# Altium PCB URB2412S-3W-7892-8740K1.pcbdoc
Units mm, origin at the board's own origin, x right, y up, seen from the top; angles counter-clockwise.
Board outline 23.7 x 14.8 mm, 2 copper layers (Top Layer, Bottom Layer), stack 0.78 mm thick; 27 components, 19 nets, 72 pads, 28 vias.
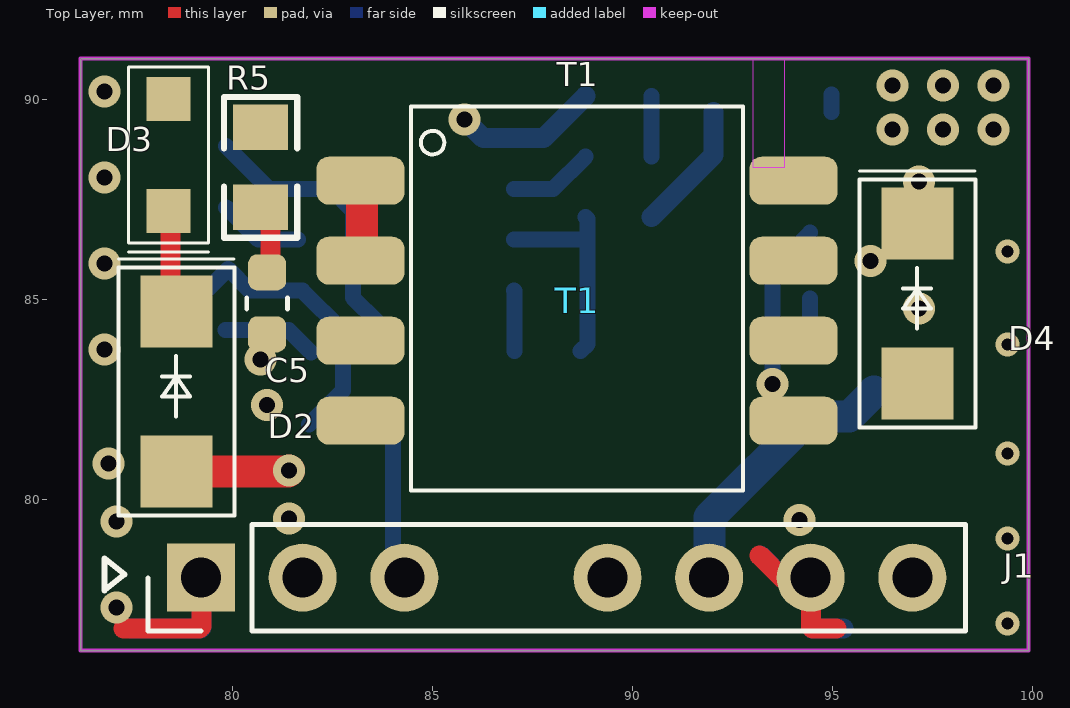
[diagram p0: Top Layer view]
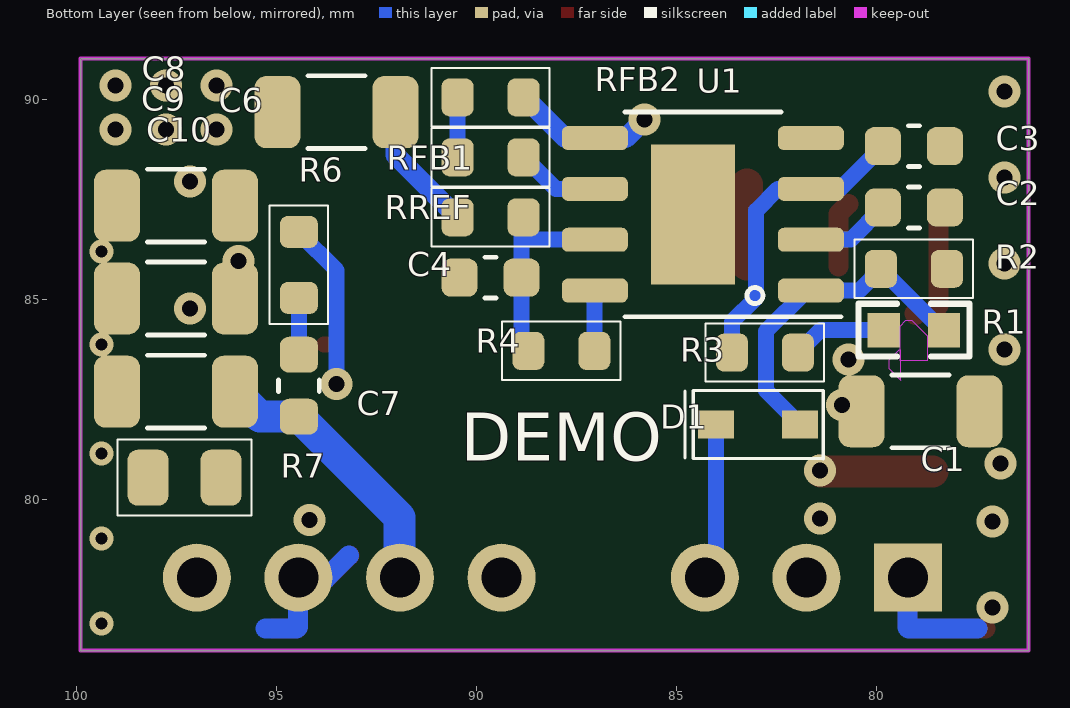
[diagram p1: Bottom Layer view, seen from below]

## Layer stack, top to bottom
Top Solder Mask Layer: solder mask 0.01, Dk 3.3
Top Layer: signal copper 0.035
Dielectric2: surface 0.71, FR4, Dk 4.5
Bottom Layer: signal copper 0.035
Bottom Solder Mask Layer: solder mask 0.01, Dk 3.3

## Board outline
76.2,91.02 99.9,91.02 99.9,76.22 76.2,76.22

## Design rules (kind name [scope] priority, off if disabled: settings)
BoardOutlineClearance copperThickness1oz [All] p0: genericclearance=0.254 ignorepadtopadclearanceinfootprint=FALSE except(0: Arc-SplitContinuation Track-SplitContinuation SMDPad-SplitContinuation THPad-SplitContinuation Via-SplitContinuation Fill-SplitContinuation Poly-SplitContinuation Region-SplitContinuation Text-SplitContinuation)
BoardOutlineClearance otherClearance [All] p0: genericclearance=0.254 ignorepadtopadclearanceinfootprint=FALSE except(0: Arc-SplitContinuation Track-SplitContinuation SMDPad-SplitContinuation THPad-SplitContinuation Via-SplitContinuation Fill-SplitContinuation Poly-SplitContinuation Region-SplitContinuation Text-SplitContinuation)
Clearance copperThickness1oz [All] p1: gap=0.178 ignorepadtopadclearanceinfootprint=FALSE
Clearance otherClearance [All] p1: gap=0.178 ignorepadtopadclearanceinfootprint=FALSE
DiffPairsRouting differentialPair [All] p1: maxuncoupledlength=10 minlimit=5 maxlimit=Infinity mostfreqgap=6 toplayer_minwidth=5 toplayer_prefwidth=100 toplayer_maxwidth=100 bottomlayer_minwidth=5 bottomlayer_prefwidth=100 bottomlayer_maxwidth=100
PasteMaskExpansion pasteMaskExpansion [All] p1: expansion=0
PlaneConnect innerPlane [All] p1: planeconnectstyle=Relief reliefexpansion=0.508 reliefentries=4 reliefconductorwidth=0.254 reliefairgap=0.254
PolygonConnect copper0 [All] p1: connectstyle=Relief reliefentries=4 reliefconductorwidth=19.685 polygonreliefangle="90 Angle" airgapwidth=19.685
PolygonConnect copper1 [All] p1: connectstyle=Direct reliefentries=4 reliefconductorwidth=10 polygonreliefangle="90 Angle" airgapwidth=10
RoutingVias viaSize [All] p1: viastyle="Through Hole" holewidth=24 minholewidth=11.811 maxholewidth=393.7 width=24 minwidth=11.811 maxwidth=393.7
SolderMaskExpansion solderMaskExpansion [All] p1: useseparateexpansions=TRUE expansion=2 expansionbottom=2
Width copperThickness1oz [All] p1: maxlimit=100 minlimit=5 preferedwidth=10

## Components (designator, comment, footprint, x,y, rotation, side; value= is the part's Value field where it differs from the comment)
C1 "10uF" C1206 78.9,82.2 r180 bottom
C2 "1uF" C0603 79.065,87.297 r0 bottom
C3 "1uF" C0603 79.065,88.83 r180 bottom
C4 "10pF" C0603 89.65,85.543 r180 bottom
C5 "470pF" C0603 80.865,84.9 r270 top
C6 "1nF" C1206 93.5,89.68 r180 bottom
C7 "My_library_C" coileasy:C_0603 94.44,82.84 r270 bottom
C8 "22uF" C1206 97.515,87.34 r0 bottom
C9 "22uF" C1206 97.515,85.02 r0 bottom
C10 "22uF" C1206 97.515,82.69 r0 bottom
D1 "B0540WS" SOD-323_L1.8-W1.3-LS2.5-RD 82.96,81.88 r180 bottom
D2 "1SMA5930A" SMA_L4.3-W2.6-LS5.2-RD 78.6,82.7 r270 top
D3 "DSS210" SOD-123_L2.8-W1.8-LS3.7-FD 78.452,88.71 r90 top
D4 "SS38" SMA_L4.4-W2.8-LS5.4-RD 97.121,84.9 r270 top
J1 "Coileasy_Conn_01x07_1" coileasy:PinHeader_01x07_1_P2.54mm_Vertical 79.214,78.042 r90 top
R1 "" R0603#1 79.065,84.23 r0 bottom
R2 "100kΩ" R0603#2 79.065,85.763 r0 bottom
R3 "0Ω" R0603#2 82.79,83.67 r180 bottom
R4 "Coileasy_R" coileasy:R_0603 87.88,83.71 r0 bottom
R5 "" R0805#1 80.7,88.3 r90 top
R6 "Coileasy_R" coileasy:R_0603 94.44,85.86 r90 bottom
R7 "2.2kΩ" R0805#2 97.3,80.54 r0 bottom
RFB1 "120kΩ" R0603#2 89.65,88.55 r180 bottom
RFB2 "4.7kΩ" R0603#2 89.65,90.05 r0 bottom
RREF "10kΩ" R0603#2 89.65,87.05 r180 bottom
T1 "" ? 88.358,84.9 r0 top
U1 "CMP7892" ESOP-8_L4.9-W3.9-P1.27-LS6.0-BL-EP3.3 84.34,87.125 r0 bottom

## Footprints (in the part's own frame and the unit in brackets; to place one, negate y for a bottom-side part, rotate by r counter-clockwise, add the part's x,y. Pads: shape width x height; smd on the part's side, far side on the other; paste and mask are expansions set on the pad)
C0603 [mm]
  rrect50% 0.9x0.95 smd: 1(-0.775,0) 2(0.775,0)
  silkscreen extent -0.14,-0.51 0.14,0.51
C1206 [mm]
  rrect50% 1.15x1.8 smd: 1(-1.475,0) 2(1.475,0)
  silkscreen extent -0.71,-0.91 0.71,0.91
coileasy:C_0603 [mm]
  rrect50% 0.9x0.95 smd: 1(-0.775,0) 2(0.775,0)
  silkscreen extent -0.14,-0.51 0.14,0.51
coileasy:PinHeader_01x07_1_P2.54mm_Vertical [mm]
  rect 1.7x1.7 hole 1: 1(0,0)
  round 1.7 hole 1: 2(0,-2.54) 3(0,-5.08) 5(0,-10.16) 6(0,-12.7) 7(0,-15.24) 8(0,-17.78)
  silkscreen extent -1.33,-19.11 1.33,1.33
coileasy:R_0603 [mm]
  rrect50% 0.8x0.95 smd: 1(-0.825,0) 2(0.825,0)
  silkscreen extent -1.48,-0.73 1.48,0.73
ESOP-8_L4.9-W3.9-P1.27-LS6.0-BL-EP3.3 [mm]
  rrect50% 1.65x0.6 smd: 1(-2.7,1.905) 2(-2.7,0.635) 3(-2.7,-0.635) 4(-2.7,-1.905) 5(2.7,-1.905) 6(2.7,-0.635) 7(2.7,0.635) 8(2.7,1.905)
  rect 2.1x3.5 smd: 9(0.25,0)
  silkscreen extent -3.45,-2.56 1.95,2.56
R0603#1 [mm]
  rect 0.806x0.864 smd: 1(-0.753,0) 2(0.753,0)
  silkscreen extent -1.39,-0.66 1.39,0.66
R0603#2 [mm]
  rrect50% 0.8x0.95 smd: 1(-0.825,0) 2(0.825,0)
  silkscreen extent -1.48,-0.73 1.48,0.73
R0805#1 [mm]
  rect 1.133x1.377 smd: 1(-1,0) 2(1,0)
  silkscreen extent -1.76,-0.92 1.76,0.92
R0805#2 [mm]
  rrect50% 1.025x1.4 smd: 1(-0.913,0) 2(0.913,0)
  silkscreen extent -1.68,-0.95 1.68,0.95
SMA_L4.3-W2.6-LS5.2-RD [mm]
  rect 1.8x1.8 smd: 1(-2,0) 2(2,0)
  silkscreen extent -3.31,-1.45 3.1,1.45
SMA_L4.4-W2.8-LS5.4-RD [mm]
  rect 1.8x1.8 smd: 1(-2,0) 2(2,0)
  silkscreen extent -3.31,-1.45 3.1,1.45
SOD-123_L2.8-W1.8-LS3.7-FD [mm]
  rect 1.1x1.1 smd: 1(-1.5,0.05) 2(1.3,0.05)
  silkscreen extent -2.53,-0.95 2.1,1.05
SOD-323_L1.8-W1.3-LS2.5-RD [mm]
  rect 0.9x0.7 smd: 1(-1.05,-0.01) 2(1.05,-0.01)
  silkscreen extent -1.83,-0.86 1.63,0.84
? [mm]
  rrect50% 2.2x1.2 smd: 1(-5.158,3.067) 2(-5.158,1.067) 3(-5.158,-0.933) 4(-5.158,-2.933) 5(5.667,-2.933) 6(5.667,-0.933) 7(5.667,1.067) 8(5.667,3.067)
  silkscreen extent -3.9,-4.67 4.4,4.93

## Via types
v1: diameter 0.8, hole 0.4, Top Layer to Bottom Layer, 23 vias
v2: diameter 0.6, hole 0.3, Top Layer to Bottom Layer, 5 vias

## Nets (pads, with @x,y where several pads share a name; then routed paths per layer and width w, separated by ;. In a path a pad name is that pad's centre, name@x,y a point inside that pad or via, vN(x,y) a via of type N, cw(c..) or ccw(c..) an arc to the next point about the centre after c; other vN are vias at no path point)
$1N2: D4.2 R6.2 T1.5 T1.6 | length 4.5
  Top Layer w0.4: T1.6@93.52,83.87 T1.6@93.815,83.87
  Bottom Layer w0.4: v1(93.5,82.88) 93.5,85.725 R6.2@94.44,86.665
$1N7: C3.1 R3.1 U1.3 | length 7.6
  Bottom Layer w0.4: C3.1 80.91,87.76 U1.3 82.465,87.76 83.01,87.215 83.01,85.04 83.615,84.435 R3.1
$1N12: D2.1 D3.1 | length 2.5
  Top Layer w0.5: D3.1@78.45,87.13 78.45,84.85 D2.1 ; D2.1@79.02,84.61 D2.1@79.05,84.64
$1N14: C5.1 R5.1 | length 1.7
  Top Layer w0.5: R5.1@80.7,87.388 80.95,87.138 C5.1@80.95,85.825
$1N15: C2.2 U1.2 | length 2.1
  Bottom Layer w0.4: C2.2 80.647,86.49 U1.2
$1N19: J1.8
$1N21: J1.5
$1N22: RFB1.1 RFB2.2 | length 1.5
  Bottom Layer w0.4: RFB1.1@90.475,88.568 RFB2.2@90.475,90.08
$1N23: R4.1 U1.8 | length 1.5
  Bottom Layer w0.4: U1.8 87.055,85.205 R4.1
$1N27: C7.1 R6.1 | length 1.4
  Bottom Layer w0.4: C7.1 R6.1@94.44,85.015
CTRL: D1.1 J1.3 | length 4
  Bottom Layer w0.4: D1.1 84.01,78.27 J1.3@84.3,77.98
EN: D1.2 R1.1 R2.2 U1.1 | length 8.5
  Bottom Layer w0.4: R1.1@78.24,84.23 78.357,84.23 R2.2 80.433,85.22 U1.1 81.745,85.22 82.766,84.199 82.766,82.726 D1.2
GND1: C1.2 C2.1 C3.2 C4.1 C6.2 J1.1 R2.1 RREF.1 U1.4 U1.9 | length 9.3
  Top Layer w0.5: 77.274,76.77 79.17,76.77 79.22,76.82 J1.1@79.22,77.98
  Bottom Layer w0.5: 77.474,76.77 79.199,76.77 79.22,76.791 J1.1@79.22,77.98 ; RREF.1@90.475,87.055 92.025,88.605 C6.2
  other v1: 77.1,77.3 77.1,79.45 76.9,80.9 76.8,83.75 76.8,85.9 76.8,88.05 76.8,90.2
GND2: C6.1 C8.2 C9.2 C10.2 J1.7 R7.2 T1.7 T1.8 | length 7.4
  Top Layer w0.5: 93.18,78.6 93.77,78.01 94.46,78.01 94.46,76.808 94.498,76.77 95.096,76.77
  Bottom Layer w0.4: C6.1 C6.1@94.975,90.115
  Bottom Layer w0.5: 93.19,78.6 93.78,78.01 94.46,78.01 94.46,76.808 94.498,76.77 95.273,76.77
  other v1: 94.17,79.48 96.5,89.25 97.76,89.25 99.02,89.25 96.5,90.35 97.76,90.35 99.02,90.35
  other v2: 99.38,76.9 99.38,79.02 99.38,81.14 99.38,83.87 99.38,86.19
RFB: RFB1.2 U1.6 | length 2.1
  Bottom Layer w0.4: U1.6 88.017,87.76 RFB1.2@88.825,88.568
RREF: C4.2 R4.2 RREF.2 U1.7 | length 5.3
  Bottom Layer w0.4: U1.7 88.865,86.49 88.875,86.48 ; R4.2 88.875,83.88 C4.2 88.875,86.48 ; RREF.2@88.825,87.055 88.875,87.005 88.875,86.48
SW: D3.2 R5.2 RFB2.1 T1.1 T1.2 U1.5 | length 5.7
  Top Layer w0.8: T1.2@83.24,85.87 T1.1@83.24,87.87
  Bottom Layer w0.5: v1(85.8,89.5) 86.27,89.03 U1.5 87.775,89.03 RFB2.1@88.825,90.08
VIN: C1.1 C5.2 D2.2 J1.2 R1.2 R3.2 T1.3 T1.4 | length 5.2
  Top Layer w0.8: D2.2 81.39,80.7 v1(81.41,80.72)
  Bottom Layer w0.399: R1.2 81.405,84.23 R3.2
  other v1: 81.41,79.52 80.865,82.36 80.7,83.5
VOUT: C7.2 C8.1 C9.1 C10.1 D4.1 J1.6 R7.1 | length 7
  Bottom Layer w0.8: J1.6@91.92,77.95 91.92,79.545 C7.2 95.415,82.065 C10.1
  other v1: 97.167,84.773 95.948,85.963 97.167,87.948

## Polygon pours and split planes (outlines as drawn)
GND2 on Bottom Layer (solid, remove dead copper, pour order 18): 99.9,79.873 99.9,76.2 92.9,76.2 92.81,76.29 92.81,79.23 93.453,79.873
GND1 on Top Layer (solid, remove dead copper, pour order 4): 76.2,78.868 76.2,91 77.513,91 77.5,86 77.5,79.425 80.1,79.425 80.1,78.818
GND1 on Top Layer (solid, remove dead copper, pour order 6): 76.2,79.2 80.1,79.2 80.1,76.2 76.2,76.2
GND1 on Bottom Layer (solid, remove dead copper, pour order 24): 76.2,80.3 80.1,80.3 80.1,76.2 76.2,76.2
GND2 on Top Layer (solid, remove dead copper, pour order 10): 95.2,85.3 93,85.3 93,90.8 95.8,90.8 95.8,88.24 95.2,88.24
GND2 on Bottom Layer (solid, remove dead copper, pour order 28): 94.4,91 99.9,91 99.9,79.8 99.9,79.7 97.9,79.7 97.9,88.6 94.4,88.6
VOUT on Bottom Layer (solid, remove dead copper, pour order 30): 97.25,79.85 95.33,79.85 95.33,88.44 97.25,88.44
VOUT on Top Layer (solid, remove dead copper, pour order 16): 95.35,84.084 95.35,88.46 98.8,88.46 98.8,84.084
$1N2 on Top Layer (solid, remove dead copper, pour order 18): 92.9,81.43 92.9,83.757 98.8,83.757 98.8,81.43
SW on Top Layer (solid, remove dead copper, pour order 20): 77.9,90.455 86.35,90.455 86.35,88.63 84.275,88.63 84.275,87.23 82.219,87.23 82.219,88.68 77.9,88.68
GND1 on Bottom Layer (solid, remove dead copper, pour order 38): 85.64,86.5 85.64,82.88 85.65,82.88 87.51,82.88 89.39,82.88 89.9,83.4 89.9,87.6 90.9,87.6 90.9,82.5 90.4,82 84.7,82 84.6,82.1 84.6,84.1 84.3,84.4 84.2,84.4 83.54,85.06 83.54,86.5
GND2 on Top Layer (solid, remove dead copper, pour order 24): 93,85.53 93,90.98 99.9,90.98 99.9,76.2 92.9,76.2
GND1 on Bottom Layer (solid, remove dead copper, pour order 42): 80.1,80 76.2,80 76.2,91 85.3,91 85.3,88.1 85.2,88 83.1,88 82.4,88.7 80.1,88.7
VIN on Bottom Layer (solid, remove dead copper, pour order 44): 80.4,76.3 80.4,81.5 79.5,81.5 79.5,84.6 79.6,84.7 82.2,84.7 82.6,84.3 82.6,76.2 80.5,76.2
VIN on Top Layer (solid, remove dead copper, pour order 30): 82.6,76.2 80.5,76.2 80.4,76.2 80.4,84.5 84.4,84.5 84.4,81 82.6,81

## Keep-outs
Top Layer:
  region: 93,88.3 93.8,88.3 93.8,91 93,91
Bottom Layer:
  region: 78.72,83.476 78.72,84.075 79.105,84.46 79.28,84.46 79.42,84.32 79.42,83.476
  region: 79.39,82.98 79.39,83.73 79.44,83.73 79.69,83.48 79.69,83.28
Board Outline Layer:
  the board outline again, w0.1

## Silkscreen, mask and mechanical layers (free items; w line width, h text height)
Top Silkscreen Layer:
  lines w0.15: 76.8,77.725 76.8,78.525 77.3,78.125 76.8,77.725
Bottom Silkscreen Layer:
  text "DEMO" at 90.39,80.963 h1.2
Bottom Assembly Layer:
  region: 97.2,90.88 99.09,90.88 99.09,88.57 97.2,88.57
